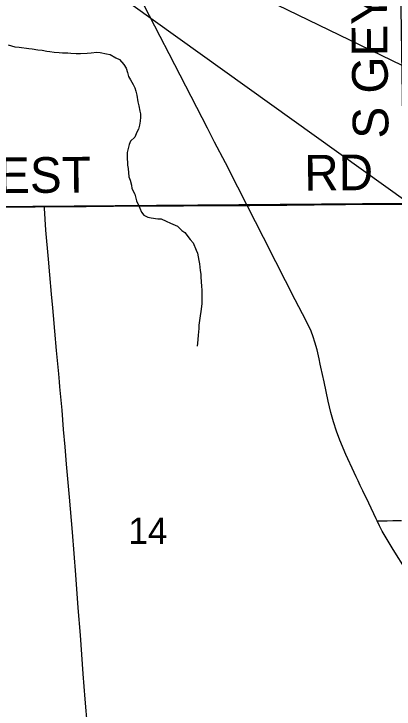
# Model space of a CAD drawing. Extents: x 0 to 34, y 0 to 22.
# Drawn here: x 21.677 to 22.282, y 11.815 to 12.923 of the extents above; entities that cross this region are included whole.
import ezdxf

# ---------------------------------------------------------------- set-up
doc = ezdxf.new("R2010")
doc.units = 0
for name, color, linetype in [('GM_X_County_Road', 7, 'Continuous'), ('GM_X_County_Road_Text', 7, 'Continuous'), ('GM_X_Minor_River', 7, 'Continuous'), ('GM_X_Section', 7, 'Continuous'), ('GM_X_Section_Text', 7, 'Continuous'), ('GM_X_Township_Road', 7, 'Continuous'), ('GM_X_Township_Road_Text', 7, 'Continuous'), ('SH_Text', 7, 'Continuous')]:
    doc.layers.add(name, color=color, linetype=linetype)

msp = doc.modelspace()

# ---------------------------------------------------------------- linework, layer by layer
at = {"layer": 'GM_X_County_Road'}
for points in [[(22.0484, 12.6176), (22.0334, 12.6468), (22.0137, 12.6856), (21.9963, 12.7186), (21.9851, 12.7407), (21.968, 12.7738), (21.9242, 12.8594), (21.9098, 12.8871), (21.8755, 12.9533), (21.8613, 12.9809), (21.8526, 12.9975), (21.8478, 13.0055), (21.8442, 13.0107), (21.8404, 13.0156), (21.8361, 13.0202), (21.8315, 13.0245), (21.8265, 13.0283), (21.8212, 13.0317), (21.8131, 13.0364), (21.8021, 13.0419), (21.7933, 13.0459)], [(21.7254, 12.6158), (21.742, 12.616), (21.7917, 12.6161), (21.8352, 12.6165), (21.8974, 12.6169), (21.9471, 12.6172), (21.9909, 12.6175), (22.0216, 12.6176), (22.0484, 12.6176)], [(22.0484, 12.6176), (22.0527, 12.6176), (22.1116, 12.6184), (22.1303, 12.6185), (22.1551, 12.6189), (22.2049, 12.6192), (22.267, 12.6197), (22.2919, 12.6199), (22.2969, 12.6199)], [(22.2553, 12.1152), (22.2537, 12.1183), (22.2418, 12.1436), (22.2322, 12.1632), (22.2281, 12.1715), (22.2247, 12.1789), (22.2218, 12.1851), (22.2153, 12.1991), (22.2084, 12.2142), (22.2054, 12.2209), (22.1959, 12.2437), (22.1903, 12.2581), (22.1858, 12.2729), (22.1816, 12.2878), (22.1772, 12.3059), (22.1708, 12.3365), (22.1657, 12.3601), (22.1646, 12.3648), (22.1628, 12.3734), (22.1595, 12.3875), (22.1562, 12.3997), (22.1533, 12.4086), (22.1499, 12.4173), (22.1446, 12.4286), (22.1361, 12.4452), (22.1246, 12.4672), (22.1092, 12.4974), (22.0938, 12.5278), (22.0743, 12.5667), (22.049, 12.6165), (22.0484, 12.6176)], [(21.4079, 12.6129), (21.4163, 12.613), (21.4305, 12.6131), (21.4487, 12.6133), (21.4564, 12.6134), (21.4689, 12.6135), (21.4759, 12.6136), (21.4874, 12.6137), (21.4967, 12.6138), (21.5077, 12.6139), (21.5181, 12.6139), (21.528, 12.614), (21.5434, 12.6141), (21.5743, 12.6141), (21.5992, 12.6145), (21.6767, 12.6153), (21.7109, 12.6156), (21.7254, 12.6158)], [(22.5536, 11.616), (22.5355, 11.6502), (22.5139, 11.6915), (22.4919, 11.7326), (22.4757, 11.7627), (22.4634, 11.7843), (22.4475, 11.8111), (22.436, 11.8296), (22.4072, 11.8738), (22.3935, 11.8946), (22.3817, 11.9128), (22.3681, 11.9336), (22.3424, 11.9725), (22.3219, 12.0037), (22.2805, 12.0694), (22.2709, 12.0853), (22.2634, 12.0989), (22.2591, 12.1073), (22.2553, 12.1152)]]:
    msp.add_lwpolyline(points, dxfattribs=at)
at = {"layer": 'GM_X_Minor_River'}
for points in [[(21.6679, 12.8736), (21.6782, 12.8707), (21.6854, 12.8701), (21.7007, 12.868), (21.706, 12.8673), (21.7148, 12.8659), (21.7216, 12.8649), (21.7293, 12.8638), (21.7342, 12.8631), (21.7407, 12.8617), (21.7487, 12.8614), (21.754, 12.8611), (21.7628, 12.8609), (21.7673, 12.8605), (21.7761, 12.8599), (21.7826, 12.8596), (21.7932, 12.8605), (21.7997, 12.861), (21.8088, 12.8618), (21.8141, 12.8612), (21.824, 12.8594), (21.8301, 12.8583), (21.8393, 12.8531), (21.8447, 12.8505), (21.8516, 12.8423), (21.8555, 12.8363), (21.8575, 12.8294), (21.8591, 12.8234), (21.8626, 12.8177), (21.8665, 12.8102), (21.8696, 12.8053), (21.8712, 12.7996), (21.8728, 12.7932), (21.8741, 12.7829), (21.8757, 12.7765), (21.8773, 12.7682), (21.8785, 12.7636), (21.8786, 12.7583), (21.8779, 12.7522), (21.8768, 12.7454), (21.875, 12.7393), (21.8728, 12.7343), (21.8695, 12.7263), (21.8627, 12.7201), (21.8605, 12.7148), (21.8569, 12.7022), (21.8569, 12.6961), (21.8575, 12.6821), (21.8587, 12.6764), (21.86, 12.6631), (21.862, 12.6578), (21.864, 12.6502), (21.8645, 12.6445), (21.8691, 12.6355), (21.8719, 12.6249), (21.8751, 12.6181), (21.8774, 12.6132), (21.8798, 12.6068), (21.8837, 12.6023), (21.8898, 12.5993), (21.8955, 12.5982)], [(21.8955, 12.5982), (21.9058, 12.5965), (21.9115, 12.5962), (21.9191, 12.5929), (21.9264, 12.5895), (21.9375, 12.5847), (21.9441, 12.578), (21.949, 12.5746), (21.9572, 12.5637), (21.9622, 12.5581), (21.9669, 12.5464), (21.9692, 12.5419), (21.9713, 12.5301), (21.9725, 12.5248), (21.9734, 12.5142), (21.9742, 12.5081), (21.9743, 12.5032), (21.9753, 12.4891), (21.9761, 12.4827), (21.9763, 12.4683), (21.976, 12.461), (21.9743, 12.4489), (21.9732, 12.4416), (21.9715, 12.4268), (21.9712, 12.4219), (21.9702, 12.4108), (21.9695, 12.404), (21.9692, 12.3983), (21.9685, 12.3933)]]:
    msp.add_lwpolyline(points, dxfattribs=at)
at = {"layer": 'GM_X_Section'}
for points in [[(22.2822, 13.6222), (22.2979, 12.6206), (21.3125, 12.6129), (21.2938, 13.6104)], [(21.3125, 12.6129), (22.2979, 12.6206), (22.3015, 11.617), (21.2987, 11.6032), (21.3118, 11.9349)]]:
    msp.add_lwpolyline(points, close=True, dxfattribs=at)
at = {"layer": 'GM_X_Township_Road'}
for points in [[(21.794, 11.7876), (21.7903, 11.8309), (21.7873, 11.8712), (21.7827, 11.9332), (21.7793, 11.9765), (21.7754, 12.0292), (21.77, 12.0973), (21.7653, 12.1531), (21.7607, 12.2055), (21.7582, 12.2331), (21.7558, 12.2609), (21.7534, 12.2918), (21.752, 12.3075), (21.7501, 12.3287), (21.7493, 12.3369), (21.7481, 12.3496), (21.7447, 12.3865), (21.7419, 12.4175), (21.7398, 12.4423), (21.7387, 12.4546), (21.7367, 12.4763), (21.7339, 12.5072), (21.7319, 12.5319), (21.7279, 12.5784), (21.7256, 12.6132), (21.7254, 12.6158)], [(22.2553, 12.1152), (22.2585, 12.1154), (22.2709, 12.1154), (22.2801, 12.1155), (22.2942, 12.1157)]]:
    msp.add_lwpolyline(points, dxfattribs=at)
at = {"layer": 'SH_Text'}
msp.add_lwpolyline([(22.8565, 12.5686), (21.3852, 13.2813), (22.8565, 12.227)], close=True, dxfattribs=at)

# ---------------------------------------------------------------- texts
at = {"layer": 'GM_X_County_Road_Text'}
for s, rotation, p in [('SECREST', 0.4761, (21.4407, 12.6355)), ('RD', 0.4784, (22.1393, 12.6413))]:
    msp.add_text(s, height=0.05682, rotation=rotation, dxfattribs=at).set_placement(p)
at = {"layer": 'GM_X_Section_Text'}
msp.add_text('14', height=0.04186, rotation=0, dxfattribs=at).set_placement((21.8591, 12.0785))
at = {"layer": 'GM_X_Township_Road_Text'}
msp.add_text('S GEYERS', height=0.05682, rotation=90.7292, dxfattribs=at).set_placement((22.2734, 12.7245))

doc.saveas('drawing.dxf')
